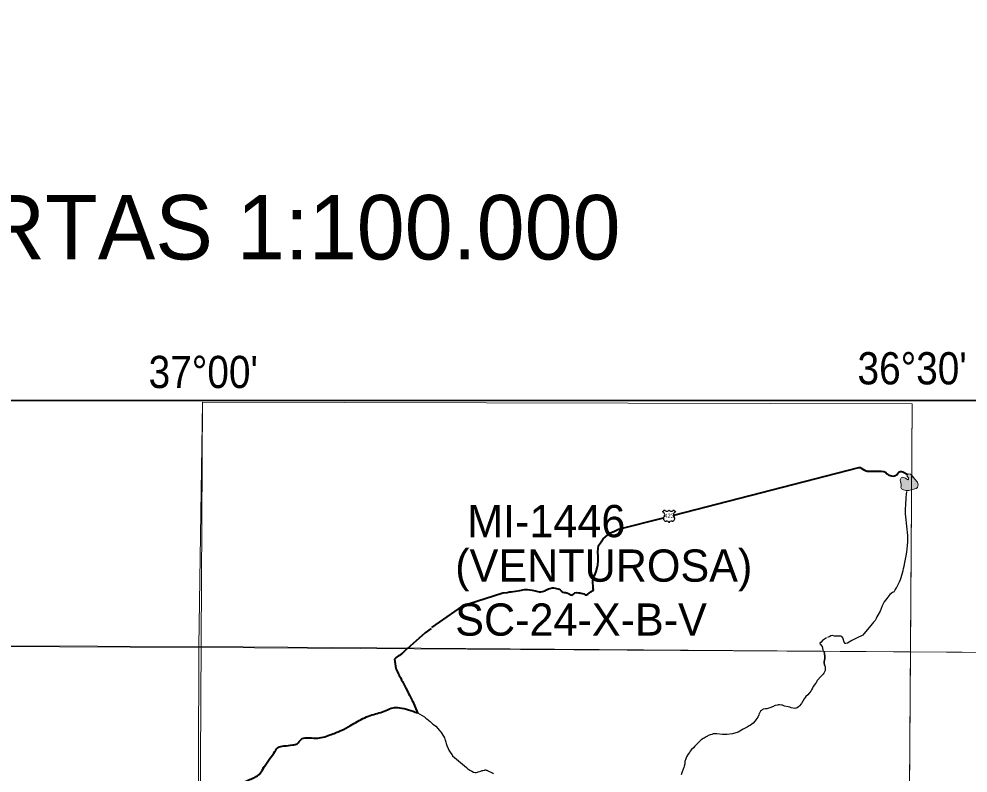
# Model space of a CAD drawing. Extents: x -1643653 to 4543381, y 1624270 to 13878484.
# Drawn here: x 604813 to 619526, y 8918990 to 8930690 of the extents above; entities that cross this region are included whole.
import ezdxf
from ezdxf.enums import TextEntityAlignment as Align

# ---------------------------------------------------------------- set-up
doc = ezdxf.new("R2010")
doc.units = 0
doc.header["$LTSCALE"] = 200
doc.layers.add('6', color=7, linetype='Continuous', lineweight=13)
doc.layers.add('60', color=7, linetype='Continuous', lineweight=13)

msp = doc.modelspace()

# ---------------------------------------------------------------- hatches: boundary and pattern name
at = {"layer": '6'}
msp.add_hatch(color=256, dxfattribs=at).paths.add_polyline_path([(618590.4, 8923622.6), (618579.9, 8923599.2), (618603.3, 8923569.1), (618601.9, 8923550), (618595.2, 8923541.4), (618555.1, 8923567.6), (618516.4, 8923579.6), (618490.1, 8923569.1), (618473.9, 8923540.4), (618479.6, 8923509.8), (618492, 8923472.6), (618488.2, 8923448.2), (618485.8, 8923418.6), (618496.8, 8923398.6), (618526.4, 8923383.3), (618561.3, 8923372.8), (618610, 8923374.2), (618666.8, 8923390.9), (618723.7, 8923405.7), (618745.6, 8923421), (618754.2, 8923461.6), (618742.3, 8923501.7), (618701.7, 8923551.9), (618664, 8923597.7), (618633.9, 8923625.4), (618610.5, 8923632.6)])

# ---------------------------------------------------------------- linework, layer by layer
at = {"layer": '6', "lineweight": 25}
for p, q in [((614790.2, 8923043.1), (614822.1, 8923075.1)), ((614962, 8923075.1), (614994, 8923043.1))]:
    msp.add_line(p, q, dxfattribs=at)
at = {"layer": '6', "lineweight": 35}
msp.add_lwpolyline([(574695.3, 8924769.6), (626625.7, 8924769.6), (626625.7, 8896026.7), (574695.3, 8896026.7)], close=True, dxfattribs=at)
at = {"layer": '6'}
for points in [[(607657.7, 8924743.3), (607574.2, 8909874.9), (607492.3, 8896026.7)], [(618663, 8924716.1), (618558.3, 8909803.7), (618456.5, 8896026.7)], [(574684.9, 8921064.7), (596639.8, 8920989.8), (607636.3, 8920937.2), (626625.7, 8920820.5)], [(608653.2, 8919135.4), (608627.5, 8919108.1), (608598.7, 8919080.5), (608588.5, 8919064.1), (608579.3, 8919042.5), (608574.7, 8919033.7)]]:
    msp.add_lwpolyline(points, dxfattribs=at)
for points in [[(607657.7, 8924743.3), (618663, 8924716.1), (618636, 8920869.6), (607600.8, 8920952.4)], [(618590.4, 8923622.6), (618579.9, 8923599.2), (618603.3, 8923569.1), (618601.9, 8923550), (618595.2, 8923541.4), (618555.1, 8923567.6), (618516.4, 8923579.6), (618490.1, 8923569.1), (618473.9, 8923540.4), (618479.6, 8923509.8), (618492, 8923472.6), (618488.2, 8923448.2), (618485.8, 8923418.6), (618496.8, 8923398.6), (618526.4, 8923383.3), (618561.3, 8923372.8), (618610, 8923374.2), (618666.8, 8923390.9), (618723.7, 8923405.7), (618745.6, 8923421), (618754.2, 8923461.6), (618742.3, 8923501.7), (618701.7, 8923551.9), (618664, 8923597.7), (618633.9, 8923625.4), (618610.5, 8923632.6)], [(607600.8, 8920952.4), (596639.8, 8920989.8), (596608.8, 8909934.4), (607569.8, 8909894.9)], [(618636, 8920869.6), (626625.7, 8920820.5), (626625.7, 8909822.1), (618558.7, 8909851.2)]]:
    msp.add_lwpolyline(points, close=True, dxfattribs=at)
at = {"layer": '6', "lineweight": 40}
for points in [[(614964.2, 8922992.9), (617832.6, 8923732.6), (617846.7, 8923732.8), (617858.9, 8923730.9), (617871.2, 8923721), (617893.7, 8923707.2), (617921.3, 8923691.5), (617934.6, 8923682.6), (617949.8, 8923677.8), (617965, 8923676), (618178.8, 8923671.4), (618220.3, 8923669), (618246.8, 8923657.3), (618269.5, 8923633.4), (618301.1, 8923613.7), (618341.8, 8923600.2), (618367.2, 8923594.5), (618405.5, 8923607.3), (618420.6, 8923616.6), (618432.5, 8923630.9), (618446.4, 8923654.4), (618458.4, 8923663.7), (618473.5, 8923670), (618492.7, 8923668.3), (618517.1, 8923664.6), (618591.3, 8923622.3)], [(611214.5, 8921246.7), (611690.9, 8921581.7), (611739.2, 8921604.7), (611780.6, 8921615.4), (612315.8, 8921783.7), (612380.5, 8921791.8), (612418.8, 8921801.5), (612446.2, 8921801.9), (612579.5, 8921823.3), (612649.2, 8921836.5), (612665.4, 8921838.8), (612696.8, 8921839.3), (612734.3, 8921834.8), (612769.8, 8921828.3), (612794.3, 8921820.6), (612836.9, 8921811.2), (612878.6, 8921802.8), (612904.9, 8921800.2), (612931.2, 8921805.6), (612968.5, 8921819.4), (612991.5, 8921833.9), (613020.7, 8921847.5), (613043.9, 8921853.9), (613078.2, 8921864.6), (613100.5, 8921863.9), (613172.6, 8921848.9), (613187.9, 8921842.1), (613203.2, 8921832.2), (613213.5, 8921824.3), (613217.6, 8921816.3), (613223.8, 8921806.3), (613239.2, 8921795.4), (613263.6, 8921790.7), (613283.8, 8921790), (613306.2, 8921786.3), (613333.6, 8921777.7), (613370.4, 8921757.1), (613391.7, 8921751.3), (613410.8, 8921764.8), (613432.7, 8921788.4), (613459, 8921792.8), (613487.4, 8921786.2), (613506.7, 8921785.5), (613523.9, 8921782.7), (613547.3, 8921778.1), (613567.7, 8921770.3), (613590.2, 8921755.5), (613610.5, 8921752.8), (613631.6, 8921763.2), (613655.6, 8921783.8), (613674.6, 8921799.3), (613688.6, 8921808.6), (613703.7, 8921814.9), (613713.7, 8921824.2), (613717.6, 8921837.4), (613713.3, 8921852.5), (613712.8, 8921885.8), (613707.8, 8921948.4), (613715.8, 8922026.4), (613743.5, 8922073.3), (613761, 8922118.1), (613780.1, 8922192.2), (613785.2, 8922213.2), (613792, 8922289.4), (613792.2, 8922338.9), (613787.9, 8922425.8), (613790.3, 8922468.3), (613797.6, 8922523), (613826.5, 8922560.8), (613869.1, 8922624.2), (613980.1, 8922716.9), (614036.5, 8922740.1), (614074.7, 8922760.9), (614109.9, 8922772.6), (614804.5, 8922951.7)], [(611201.4, 8921234.4), (611108.7, 8921166), (610832.8, 8920916.1)], [(610827.8, 8920917.6), (610823, 8920914), (610762.1, 8920855.7), (610749.5, 8920841.5), (610740.9, 8920836.9), (610713, 8920816.2), (610698.2, 8920806.3), (610662.6, 8920780.4), (610653.5, 8920774.9), (610648.2, 8920770.6), (610634.6, 8920757.1)], [(610634.6, 8920757.1), (610655.2, 8920612.5), (610665.4, 8920591.1), (610678.2, 8920567.9), (610682, 8920558.9), (610694.4, 8920535.7), (610709.7, 8920504), (610719.3, 8920486.7), (610726, 8920471.9), (610739.4, 8920447.4), (610745.8, 8920433.2), (610758.2, 8920410.6), (610809.7, 8920308.8), (610840.7, 8920249.1), (610850, 8920232.8), (610852.7, 8920225.4), (610867.4, 8920199.1), (610898.1, 8920137.8), (610910.3, 8920115.9), (610916.7, 8920101.6), (610989.7, 8919925.2)]]:
    msp.add_lwpolyline(points, dxfattribs=at)
at = {"layer": '6', "lineweight": 25}
for points in [[(618385.8, 8921803.1), (618379.3, 8921802.6), (618357.2, 8921792.1), (618316.2, 8921761.1), (618268.5, 8921697.7), (618226.7, 8921644.5), (618197.2, 8921585.4), (618177.6, 8921543.6), (618164, 8921504), (618129.5, 8921438.8), (618113.7, 8921413.2), (618101.9, 8921385.8), (618086.1, 8921356.2), (618063.2, 8921330.6), (618043.2, 8921312), (617913, 8921148.2), (617895, 8921131.8), (617799.5, 8921081.7), (617778.4, 8921071.3), (617725.1, 8921044.2), (617655.8, 8921005.7), (617632.6, 8921001.2), (617620.5, 8921001), (617607, 8921022.1), (617592.1, 8921070.3), (617586.7, 8921090.5), (617572.3, 8921107.4), (617556, 8921116.3), (617517.5, 8921115.6), (617491.2, 8921112.2), (617455.8, 8921114.7), (617418.2, 8921122.1), (617400, 8921119.8), (617381.9, 8921110.4), (617345.8, 8921092.5)], [(617334.2, 8921086.1), (617270.4, 8921047), (617247.5, 8921019.3), (617230.5, 8921004.9), (617231.8, 8920988.8), (617263.7, 8920954.9), (617272.2, 8920926.8), (617283, 8920878)], [(617303, 8920665.4), (617309.3, 8920639.1), (617311.5, 8920622.3), (617313.5, 8920613.9), (617313.6, 8920598.5), (617309.4, 8920583), (617298.1, 8920552.1), (617290.2, 8920537.8), (617278.2, 8920522.3), (617239.5, 8920482.6), (617196.2, 8920435), (617188.5, 8920425.5), (617182.5, 8920416.2), (617169.7, 8920388.5), (617163.2, 8920380.5), (617127.8, 8920330.6), (617112.8, 8920304.9), (617101.5, 8920282.3), (617087.7, 8920260.7), (617065.5, 8920231.4), (617042.8, 8920204.7), (617013.1, 8920175.2), (617003.5, 8920164.7), (616988.6, 8920143.8), (616945.6, 8920070.1), (616939.6, 8920064.2), (616914.7, 8920032.8), (616900.5, 8920019.1), (616878.8, 8920003.5), (616863.5, 8919995.6), (616858.6, 8919994.5), (616837.8, 8919993.2), (616816.9, 8919996.3), (616783.4, 8920002.8), (616773, 8920006.6), (616763.5, 8920011.1), (616735.6, 8920015.5), (616683.6, 8920028.8), (616669.3, 8920035.2), (616647.7, 8920042.1), (616635, 8920043.9), (616602.2, 8920045.9), (616583.8, 8920046.3), (616574.1, 8920045.7), (616539, 8920038.2), (616523, 8920032.3), (616509.2, 8920023.2), (616495.5, 8920017.5)], [(616495.5, 8920017.5), (616453.3, 8920000), (616409.4, 8919988.9), (616397.5, 8919986.6), (616384.8, 8919985.4), (616353, 8919979.2), (616343.8, 8919975.8), (616333.6, 8919969.7), (616322.5, 8919960.4), (616311.1, 8919948.7), (616302.5, 8919938.1), (616291.5, 8919919.8), (616291, 8919912.9), (616282.8, 8919891.9), (616271.9, 8919869.4), (616271.1, 8919865.5), (616268.5, 8919861.9), (616266.1, 8919856.8), (616238.5, 8919814.9), (616227.3, 8919799.4), (616193, 8919764.1), (616173.5, 8919748.5), (616148.1, 8919730.4), (616131, 8919720.4), (616100.8, 8919700.3), (616073.8, 8919685.1), (616060.5, 8919679.7), (616039.2, 8919669)], [(610989.7, 8919925.2), (611098.4, 8919862.7), (611123, 8919843.5), (611135.6, 8919830.6), (611185.4, 8919791.8), (611226, 8919753.4), (611227.9, 8919750.7), (611254.6, 8919731.6), (611274, 8919715.5), (611334.2, 8919651.6), (611344.9, 8919639.3), (611360, 8919618.6), (611370.7, 8919602.3), (611407.8, 8919535.5), (611413.8, 8919514.2), (611418, 8919503.3), (611429.4, 8919467.6), (611437.3, 8919447.9), (611446.9, 8919416.8), (611465.8, 8919371.6)], [(616039.2, 8919669), (615963.3, 8919626.9), (615874.3, 8919597.3), (615786, 8919586), (615718.6, 8919590.7), (615634.3, 8919599.2), (615608.5, 8919599.2), (615576.6, 8919596), (615554.8, 8919590.4), (615530.2, 8919581.5), (615515.4, 8919577.2), (615465.2, 8919552.7), (615436.7, 8919533.6), (615420.6, 8919524.9), (615405.8, 8919513.6), (615400, 8919511.3), (615384.8, 8919499.5), (615340.1, 8919452.8), (615328, 8919441.6), (615316.8, 8919433.2), (615291.1, 8919406.3), (615270.9, 8919383.5), (615241.8, 8919353.8), (615220.6, 8919327.1), (615210.8, 8919311.4), (615187.3, 8919281.6), (615162.8, 8919242), (615149.2, 8919208.9), (615137.5, 8919168), (615134.8, 8919161.3), (615133.6, 8919146.7), (615134.7, 8919133.5), (615126.3, 8919098.2), (615118.1, 8919074.2), (615109.5, 8919052.6), (615097.1, 8919008.6), (615080.7, 8918964.7)], [(611465.8, 8919371.6), (611476.9, 8919345.1), (611479.5, 8919342.7), (611508.7, 8919298.4), (611528.6, 8919273.8), (611536.4, 8919259)], [(611536.4, 8919259), (611753.5, 8919076.8), (611755.2, 8919073), (611761.1, 8919065.5), (611773.8, 8919054.2), (611802.2, 8919035.3), (611833, 8919017.3), (611858.2, 8919004.8), (611866.1, 8919002.4), (611884.7, 8919000), (611901.9, 8918999.7), (611921, 8919002.9), (611932.1, 8919006.5), (611951.6, 8919014.3), (611971.8, 8919020.1), (611994.5, 8919028.2), (612003.8, 8919030.8), (612029.9, 8919036)], [(612029.9, 8919036), (612040.2, 8919038.1), (612047.4, 8919038.5), (612058.4, 8919036.9)], [(612058.4, 8919036.9), (612068.4, 8919035.4), (612079.1, 8919029), (612083.1, 8919027)], [(612083.1, 8919027), (612129.9, 8919004.2), (612137, 8918999.2), (612151.9, 8918992.2), (612169.6, 8918981.6)]]:
    msp.add_lwpolyline(points, dxfattribs=at)
at = {"layer": '6', "lineweight": 35}
msp.add_lwpolyline([(617294.2, 8920878.4), (617302.4, 8920840.9), (617306.5, 8920803.1), (617306.1, 8920783.9), (617304, 8920766.2), (617295.2, 8920713.2), (617295.4, 8920693.6), (617300.5, 8920675.8), (617303, 8920665.4)], dxfattribs=at)
at = {"layer": '6', "lineweight": 25}
for centre, radius, start, end in [((614777.7, 8922998.7), 46.1, 317.5721, 74.36886), ((614848.4, 8922941.7), 44.9, 144.73733, 264.65778), ((614857.1, 8923088.5), 37.4, 200.95927, 339.04073), ((614927, 8923088.5), 37.4, 200.95927, 339.04073), ((614935.7, 8922941.7), 44.9, 275.34222, 35.26267), ((615006.4, 8922998.7), 46.1, 105.62774, 222.4279), ((614844, 8922779), 118, 72.89371, 89.90057), ((614873.2, 8922873.7), 18.9, 357.69345, 72.92955), ((614910.9, 8922873.7), 18.9, 107.07045, 182.30655), ((614940.1, 8922779), 118, 90.09943, 107.10629)]:
    msp.add_arc(centre, radius, start, end, dxfattribs=at)
msp.add_spline([(618379.3, 8921802.6), (618451, 8921925.6), (618534.6, 8922201.8), (618593.2, 8922628.5), (618559.7, 8923013.4), (618576.4, 8923356.4)], degree=3, dxfattribs=at)
at = {"layer": '6', "lineweight": 40}
msp.add_spline([(605233.4, 8918291.8), (605425.1, 8918291.8), (605556.8, 8918274.6), (605694.1, 8918217.3), (605780, 8918168.6), (605911.6, 8918165.8), (606008.9, 8918211.6), (606114.8, 8918211.6), (606197.8, 8918134.3), (606353.7, 8918138.6), (606551.2, 8918198.7), (606637.1, 8918198.7), (606903.2, 8918104.2), (607195.1, 8918130), (607418.3, 8918172.9), (607555.7, 8918130), (607658.7, 8918138.6), (607753.1, 8918172.9), (607813.2, 8918172.9), (607967.8, 8918353.3), (608139.5, 8918542.3), (608208.1, 8918748.4), (608345.5, 8918868.7), (608508.6, 8918946), (608680.3, 8919186.5), (608766.2, 8919298.2), (608826.3, 8919384.1), (608920.7, 8919409.8), (609058.1, 8919427), (609126.8, 8919444.2), (609186.8, 8919512.9), (609272.7, 8919538.7), (609418.7, 8919530.1), (609633.3, 8919581.6), (609805, 8919650.3), (609950.9, 8919727.6), (610174.2, 8919847.9), (610285.8, 8919890.8), (610500.4, 8919959.5), (610612, 8920002.5), (610715, 8920002.5), (610989.7, 8919925.2)], degree=3, dxfattribs=at)
at = {"layer": '60', "lineweight": 25}
msp.add_spline([(814781, 9009175.5), (814787.2, 9009173.4), (814796.9, 9009173.4), (814799.4, 9009172.4), (814805.1, 9009174.5), (814805.6, 9009176.5), (814811.7, 9009179.5), (814811.7, 9009179.5), (814801.5, 9009181), (814790.7, 9009181.5), (814784.1, 9009183.1), (814777.4, 9009185.1), (814778.4, 9009175.5)], degree=3, dxfattribs=at)

# ---------------------------------------------------------------- texts
at = {"layer": '6'}
msp.add_text('ARTICULAÇÃO DAS CARTAS 1:100.000', height=1000, dxfattribs=at).set_placement((601765.5, 8926958.2), align=Align.CENTER)
for s, height, width, p in [("37°00'", 500, 0.9, (607670.1, 8924963.2)), ("36°30'", 500, 0.9, (618660.1, 8925020.1)), ('423', 70, 0.75, (614892.5, 8922945.5))]:
    msp.add_text(s, height=height, dxfattribs=dict(at, width=width)).set_placement(p, align=Align.CENTER)
for s, p in [('MI-1446', (611760.8, 8922649.4)), ('(VENTUROSA)', (611576.4, 8921958.6)), ('SC-24-X-B-V', (611576.4, 8921121.5))]:
    msp.add_text(s, height=500, dxfattribs=at).set_placement(p)

doc.saveas('drawing.dxf')
